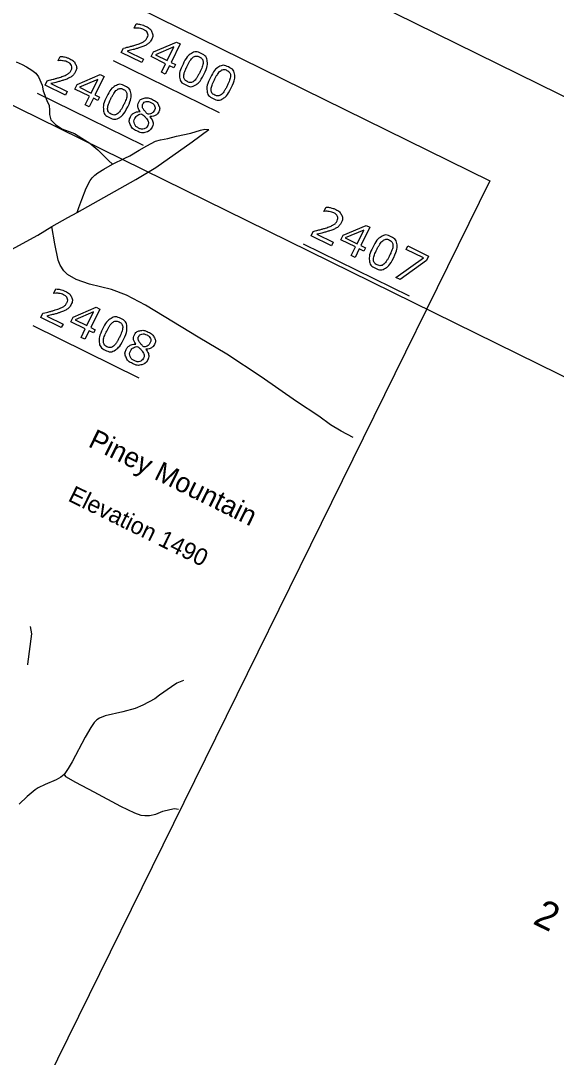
# Model space of a CAD drawing. Extents: x 1428428 to 1430511, y 857911 to 859585.
# Drawn here: x 1429265.4 to 1429384.6, y 859219.8 to 859450.7 of the extents above; entities that cross this region are included whole.
import ezdxf

# ---------------------------------------------------------------- set-up
doc = ezdxf.new("R2010")
doc.units = 0
for name, color, linetype in [('CTL Sheet Border CELL', 7, 'Continuous'), ('CTL Sheet Text', 7, 'Continuous'), ('Default', 7, 'Continuous'), ('Exist Hydrographic Misc Water Feature', 7, 'Continuous'), ('Exist Road Non-System Type 51', 7, 'Continuous'), ('Exist Road Secondary Type 51 Attributed', 7, 'Continuous'), ('Scratch_Level_3', 7, 'Continuous'), ('Sheet Title CELL', 7, 'Continuous')]:
    doc.layers.add(name, color=color, linetype=linetype)

msp = doc.modelspace()

# ---------------------------------------------------------------- linework, layer by layer
at = {"layer": 'CTL Sheet Border CELL'}
msp.add_lwpolyline([(1430484.04, 858893.65), (1429079.63, 859584.7), (1428595.9, 858601.62), (1430000.31, 857910.57)], close=True, dxfattribs=at)
at = {"layer": 'Default'}
for p, q in [((1429285.94, 859441.8), (1429309.51, 859430.2)), ((1429268.99, 859434.56), (1429292.62, 859422.93)), ((1429328.2, 859401), (1429351.8, 859389.38)), ((1429268.04, 859382.76), (1429291.67, 859371.14))]:
    msp.add_line(p, q, dxfattribs=at)
for points in [[(1429290.65, 859448.99), (1429290.6, 859449.02), (1429291.07, 859449.97)], [(1429299.47, 859440.17), (1429298.47, 859440.66), (1429297.54, 859438.77), (1429296.67, 859439.19), (1429297.61, 859441.09), (1429294.38, 859442.67), (1429294.89, 859443.71), (1429300.02, 859445.9), (1429300.85, 859445.49), (1429298.83, 859441.39), (1429299.83, 859440.89), (1429299.47, 859440.17)], [(1429292.29, 859441.35), (1429287.73, 859443.59), (1429288.2, 859444.55)], [(1429289.05, 859443.91), (1429292.67, 859442.13), (1429292.29, 859441.35)], [(1429297.96, 859441.81), (1429299.46, 859444.85), (1429295.35, 859443.1), (1429297.96, 859441.81)], [(1429273.69, 859441.76), (1429273.65, 859441.78), (1429274.11, 859442.73)], [(1429282.52, 859432.93), (1429281.52, 859433.42), (1429280.58, 859431.53), (1429279.72, 859431.95), (1429280.65, 859433.85), (1429277.42, 859435.44), (1429277.94, 859436.47), (1429283.06, 859438.67), (1429283.9, 859438.26), (1429281.87, 859434.15), (1429282.87, 859433.65), (1429282.52, 859432.93)], [(1429275.33, 859434.11), (1429270.77, 859436.35), (1429271.24, 859437.31)], [(1429272.09, 859436.67), (1429275.72, 859434.89), (1429275.33, 859434.11)], [(1429281.01, 859434.57), (1429282.5, 859437.61), (1429278.4, 859435.86), (1429281.01, 859434.57)], [(1429291.91, 859430.42), (1429291.92, 859430.45)], [(1429294.14, 859429.31), (1429294.12, 859429.28)], [(1429332.9, 859408.19), (1429332.86, 859408.22), (1429333.33, 859409.16)], [(1429341.73, 859399.37), (1429340.73, 859399.86), (1429339.8, 859397.96), (1429338.93, 859398.39), (1429339.86, 859400.29), (1429336.64, 859401.87), (1429337.15, 859402.91), (1429342.28, 859405.1), (1429343.11, 859404.69), (1429341.09, 859400.58), (1429342.09, 859400.09), (1429341.73, 859399.37)], [(1429340.22, 859401.01), (1429341.72, 859404.05), (1429337.61, 859402.3), (1429340.22, 859401.01)], [(1429334.55, 859400.55), (1429329.99, 859402.79), (1429330.45, 859403.74)], [(1429331.31, 859403.11), (1429334.93, 859401.33), (1429334.55, 859400.55)], [(1429355.67, 859397.26), (1429349.82, 859393.03), (1429348.85, 859393.51), (1429355, 859397.86), (1429351.18, 859399.74), (1429351.57, 859400.53), (1429356.17, 859398.27), (1429355.67, 859397.26)], [(1429272.75, 859389.96), (1429272.7, 859389.98), (1429273.17, 859390.93)], [(1429274.39, 859382.32), (1429269.83, 859384.56), (1429270.3, 859385.51)], [(1429281.57, 859381.14), (1429280.57, 859381.63), (1429279.64, 859379.73), (1429278.77, 859380.16), (1429279.7, 859382.05), (1429276.48, 859383.64), (1429276.99, 859384.68), (1429282.12, 859386.87), (1429282.95, 859386.46), (1429280.93, 859382.35), (1429281.93, 859381.86), (1429281.57, 859381.14)], [(1429280.06, 859382.78), (1429281.56, 859385.82), (1429277.45, 859384.06), (1429280.06, 859382.78)], [(1429271.15, 859384.88), (1429274.77, 859383.1), (1429274.39, 859382.32)], [(1429290.96, 859378.62), (1429290.97, 859378.65)], [(1429293.19, 859377.52), (1429293.18, 859377.49)]]:
    msp.add_lwpolyline(points, dxfattribs=at)
for points in [[(1429288.2, 859444.55), (1429288.87, 859444.72), (1429289.55, 859444.89), (1429290.23, 859445.06), (1429290.84, 859445.26), (1429292.12, 859445.67), (1429292.69, 859446.01), (1429293.25, 859446.34), (1429293.53, 859446.92), (1429293.79, 859447.44), (1429293.59, 859447.91), (1429293.39, 859448.38), (1429292.77, 859448.68), (1429292.36, 859448.88), (1429291.8, 859448.98), (1429291.25, 859449.07), (1429290.65, 859448.99)], [(1429291.07, 859449.97), (1429291.47, 859449.97), (1429292.07, 859449.83), (1429292.67, 859449.7), (1429293.17, 859449.45), (1429294.21, 859448.94), (1429294.55, 859448.15), (1429294.89, 859447.36), (1429294.47, 859446.51), (1429294.28, 859446.13), (1429294.02, 859445.84), (1429293.76, 859445.56), (1429293.43, 859445.35), (1429293.11, 859445.16), (1429292.74, 859445.01), (1429292.37, 859444.85), (1429291.87, 859444.69), (1429291.15, 859444.45), (1429290.42, 859444.26), (1429289.68, 859444.07), (1429289.05, 859443.91)], [(1429306.13, 859438.72), (1429305.24, 859436.91), (1429304.26, 859436.34), (1429303.27, 859435.77), (1429302.08, 859436.36), (1429300.87, 859436.95), (1429300.73, 859438.09), (1429300.6, 859439.22), (1429301.48, 859441), (1429302.36, 859442.8), (1429303.35, 859443.38), (1429304.33, 859443.96), (1429305.53, 859443.37), (1429306.74, 859442.77), (1429306.87, 859441.63), (1429307, 859440.48), (1429306.13, 859438.72)], [(1429271.24, 859437.31), (1429271.92, 859437.48), (1429272.59, 859437.65), (1429273.27, 859437.82), (1429273.88, 859438.02), (1429275.17, 859438.43), (1429275.73, 859438.77), (1429276.3, 859439.11), (1429276.58, 859439.68), (1429276.84, 859440.2), (1429276.63, 859440.67), (1429276.43, 859441.14), (1429275.81, 859441.44), (1429275.4, 859441.65), (1429274.85, 859441.74), (1429274.3, 859441.83), (1429273.69, 859441.76)], [(1429274.11, 859442.73), (1429274.51, 859442.73), (1429275.11, 859442.59), (1429275.71, 859442.46), (1429276.22, 859442.21), (1429277.25, 859441.7), (1429277.59, 859440.91), (1429277.94, 859440.13), (1429277.52, 859439.27), (1429277.33, 859438.89), (1429277.07, 859438.6), (1429276.81, 859438.32), (1429276.47, 859438.12), (1429276.16, 859437.92), (1429275.79, 859437.77), (1429275.41, 859437.61), (1429274.91, 859437.45), (1429274.2, 859437.22), (1429273.46, 859437.02), (1429272.73, 859436.83), (1429272.09, 859436.67)], [(1429303.93, 859437.25), (1429304.27, 859437.54), (1429304.57, 859438.01), (1429304.87, 859438.48), (1429305.22, 859439.17), (1429305.55, 859439.86), (1429305.75, 859440.4), (1429305.94, 859440.93), (1429305.95, 859441.36), (1429305.96, 859441.79), (1429305.78, 859442.1), (1429305.59, 859442.41), (1429305.16, 859442.62), (1429304.74, 859442.83), (1429304.37, 859442.79), (1429304.01, 859442.75), (1429303.67, 859442.48), (1429303.35, 859442.22), (1429303.03, 859441.71), (1429302.71, 859441.19), (1429302.39, 859440.55), (1429302.05, 859439.85), (1429301.86, 859439.35), (1429301.68, 859438.85), (1429301.66, 859438.39), (1429301.63, 859437.96), (1429301.81, 859437.64), (1429301.99, 859437.32), (1429302.45, 859437.1), (1429302.87, 859436.89), (1429303.24, 859436.93), (1429303.6, 859436.97), (1429303.93, 859437.25)], [(1429312.23, 859435.72), (1429311.34, 859433.91), (1429310.35, 859433.34), (1429309.37, 859432.77), (1429308.18, 859433.35), (1429306.97, 859433.95), (1429306.83, 859435.08), (1429306.7, 859436.22), (1429307.57, 859438), (1429308.46, 859439.8), (1429309.45, 859440.38), (1429310.43, 859440.96), (1429311.63, 859440.37), (1429312.84, 859439.77), (1429312.97, 859438.63), (1429313.1, 859437.48), (1429312.23, 859435.72)], [(1429310.03, 859434.25), (1429310.37, 859434.54), (1429310.67, 859435.01), (1429310.97, 859435.48), (1429311.31, 859436.17), (1429311.65, 859436.86), (1429311.85, 859437.4), (1429312.04, 859437.93), (1429312.05, 859438.36), (1429312.06, 859438.79), (1429311.88, 859439.1), (1429311.69, 859439.41), (1429311.26, 859439.62), (1429310.84, 859439.83), (1429310.47, 859439.79), (1429310.11, 859439.75), (1429309.77, 859439.47), (1429309.45, 859439.22), (1429309.13, 859438.7), (1429308.81, 859438.19), (1429308.49, 859437.55), (1429308.14, 859436.85), (1429307.96, 859436.35), (1429307.78, 859435.85), (1429307.75, 859435.39), (1429307.73, 859434.96), (1429307.91, 859434.64), (1429308.09, 859434.32), (1429308.55, 859434.1), (1429308.97, 859433.89), (1429309.34, 859433.93), (1429309.7, 859433.97), (1429310.03, 859434.25)], [(1429289.18, 859431.48), (1429288.28, 859429.67), (1429287.3, 859429.1), (1429286.31, 859428.53), (1429285.12, 859429.12), (1429283.91, 859429.71), (1429283.78, 859430.85), (1429283.64, 859431.98), (1429284.52, 859433.76), (1429285.4, 859435.56), (1429286.39, 859436.14), (1429287.38, 859436.72), (1429288.57, 859436.13), (1429289.78, 859435.54), (1429289.91, 859434.39), (1429290.04, 859433.24), (1429289.18, 859431.48)], [(1429286.98, 859430.01), (1429287.32, 859430.3), (1429287.62, 859430.77), (1429287.92, 859431.24), (1429288.26, 859431.94), (1429288.6, 859432.62), (1429288.79, 859433.16), (1429288.98, 859433.69), (1429288.99, 859434.13), (1429289.01, 859434.55), (1429288.82, 859434.86), (1429288.64, 859435.17), (1429288.21, 859435.38), (1429287.78, 859435.59), (1429287.42, 859435.55), (1429287.05, 859435.51), (1429286.71, 859435.24), (1429286.4, 859434.98), (1429286.07, 859434.47), (1429285.75, 859433.96), (1429285.44, 859433.31), (1429285.09, 859432.61), (1429284.91, 859432.11), (1429284.72, 859431.61), (1429284.7, 859431.15), (1429284.67, 859430.73), (1429284.86, 859430.41), (1429285.04, 859430.09), (1429285.49, 859429.86), (1429285.91, 859429.65), (1429286.28, 859429.69), (1429286.65, 859429.73), (1429286.98, 859430.01)], [(1429291.92, 859430.45), (1429291.52, 859431), (1429291.43, 859431.47), (1429291.34, 859431.95), (1429291.59, 859432.46), (1429291.96, 859433.22), (1429292.84, 859433.42), (1429293.71, 859433.62), (1429294.67, 859433.14), (1429295.68, 859432.65), (1429296.04, 859431.87), (1429296.41, 859431.09), (1429296.04, 859430.34), (1429295.82, 859429.89), (1429295.31, 859429.59), (1429294.81, 859429.29), (1429294.14, 859429.31)], [(1429295.15, 859430.77), (1429295.38, 859431.26), (1429295.15, 859431.73), (1429294.92, 859432.2), (1429294.34, 859432.48), (1429293.77, 859432.76), (1429293.27, 859432.67), (1429292.77, 859432.58), (1429292.55, 859432.12), (1429292.39, 859431.79), (1429292.45, 859431.47), (1429292.52, 859431.14), (1429292.8, 859430.77), (1429292.93, 859430.61), (1429293.18, 859430.32), (1429293.43, 859430.03), (1429293.68, 859429.8), (1429294.28, 859429.88), (1429294.61, 859430.12), (1429294.94, 859430.35), (1429295.15, 859430.77)], [(1429294.6, 859426.96), (1429294.17, 859426.09), (1429293.21, 859425.84), (1429292.24, 859425.6), (1429291.21, 859426.11), (1429290.12, 859426.65), (1429289.74, 859427.53), (1429289.37, 859428.41), (1429289.81, 859429.3), (1429290.08, 859429.86), (1429290.63, 859430.15), (1429291.18, 859430.44), (1429291.91, 859430.42)], [(1429293.63, 859427.33), (1429293.84, 859427.75), (1429293.78, 859428.09), (1429293.72, 859428.43), (1429293.31, 859428.94), (1429293.14, 859429.15), (1429292.93, 859429.36), (1429292.72, 859429.57), (1429292.37, 859429.93), (1429291.86, 859429.91), (1429291.43, 859429.65), (1429290.99, 859429.39), (1429290.76, 859428.91), (1429290.46, 859428.3), (1429290.68, 859427.7), (1429290.91, 859427.09), (1429291.55, 859426.78), (1429292.22, 859426.45), (1429292.78, 859426.6), (1429293.34, 859426.74), (1429293.63, 859427.33)], [(1429294.12, 859429.28), (1429294.63, 859428.7), (1429294.76, 859428.14), (1429294.9, 859427.57), (1429294.6, 859426.96)], [(1429333.33, 859409.16), (1429333.72, 859409.16), (1429334.33, 859409.03), (1429334.93, 859408.9), (1429335.43, 859408.65), (1429336.46, 859408.14), (1429336.81, 859407.35), (1429337.15, 859406.56), (1429336.73, 859405.71), (1429336.54, 859405.33), (1429336.28, 859405.04), (1429336.02, 859404.76), (1429335.68, 859404.55), (1429335.37, 859404.36), (1429335, 859404.21), (1429334.63, 859404.05), (1429334.13, 859403.89), (1429333.41, 859403.65), (1429332.67, 859403.46), (1429331.94, 859403.27), (1429331.31, 859403.11)], [(1429330.45, 859403.74), (1429331.13, 859403.92), (1429331.81, 859404.09), (1429332.49, 859404.26), (1429333.1, 859404.46), (1429334.38, 859404.87), (1429334.94, 859405.21), (1429335.51, 859405.54), (1429335.79, 859406.12), (1429336.05, 859406.64), (1429335.85, 859407.11), (1429335.65, 859407.57), (1429335.03, 859407.88), (1429334.61, 859408.08), (1429334.06, 859408.18), (1429333.51, 859408.27), (1429332.9, 859408.19)], [(1429348.39, 859397.92), (1429347.5, 859396.11), (1429346.51, 859395.54), (1429345.53, 859394.97), (1429344.34, 859395.55), (1429343.12, 859396.15), (1429342.99, 859397.28), (1429342.86, 859398.42), (1429343.73, 859400.2), (1429344.62, 859402), (1429345.6, 859402.58), (1429346.59, 859403.16), (1429347.79, 859402.57), (1429349, 859401.97), (1429349.13, 859400.83), (1429349.26, 859399.68), (1429348.39, 859397.92)], [(1429346.19, 859396.45), (1429346.53, 859396.74), (1429346.83, 859397.21), (1429347.13, 859397.68), (1429347.47, 859398.37), (1429347.81, 859399.06), (1429348, 859399.6), (1429348.2, 859400.13), (1429348.21, 859400.56), (1429348.22, 859400.99), (1429348.03, 859401.3), (1429347.85, 859401.61), (1429347.42, 859401.82), (1429347, 859402.03), (1429346.63, 859401.99), (1429346.27, 859401.95), (1429345.93, 859401.67), (1429345.61, 859401.42), (1429345.29, 859400.9), (1429344.97, 859400.39), (1429344.65, 859399.75), (1429344.3, 859399.05), (1429344.12, 859398.55), (1429343.93, 859398.05), (1429343.91, 859397.59), (1429343.89, 859397.16), (1429344.07, 859396.84), (1429344.25, 859396.52), (1429344.7, 859396.3), (1429345.13, 859396.09), (1429345.49, 859396.13), (1429345.86, 859396.17), (1429346.19, 859396.45)], [(1429270.3, 859385.51), (1429270.97, 859385.69), (1429271.65, 859385.86), (1429272.33, 859386.03), (1429272.94, 859386.23), (1429274.22, 859386.64), (1429274.79, 859386.98), (1429275.35, 859387.31), (1429275.63, 859387.89), (1429275.89, 859388.41), (1429275.69, 859388.88), (1429275.49, 859389.34), (1429274.87, 859389.65), (1429274.45, 859389.85), (1429273.9, 859389.94), (1429273.35, 859390.03), (1429272.75, 859389.96)], [(1429273.17, 859390.93), (1429273.57, 859390.93), (1429274.17, 859390.8), (1429274.77, 859390.67), (1429275.27, 859390.42), (1429276.31, 859389.91), (1429276.65, 859389.12), (1429276.99, 859388.33), (1429276.57, 859387.48), (1429276.38, 859387.09), (1429276.12, 859386.81), (1429275.86, 859386.53), (1429275.53, 859386.32), (1429275.21, 859386.13), (1429274.84, 859385.97), (1429274.47, 859385.82), (1429273.97, 859385.66), (1429273.25, 859385.42), (1429272.52, 859385.23), (1429271.78, 859385.04), (1429271.15, 859384.88)], [(1429288.23, 859379.69), (1429287.34, 859377.88), (1429286.35, 859377.31), (1429285.37, 859376.74), (1429284.18, 859377.32), (1429282.97, 859377.92), (1429282.83, 859379.05), (1429282.7, 859380.19), (1429283.57, 859381.97), (1429284.46, 859383.77), (1429285.45, 859384.35), (1429286.43, 859384.93), (1429287.63, 859384.34), (1429288.84, 859383.74), (1429288.97, 859382.6), (1429289.1, 859381.45), (1429288.23, 859379.69)], [(1429286.03, 859378.22), (1429286.37, 859378.51), (1429286.67, 859378.98), (1429286.97, 859379.44), (1429287.31, 859380.14), (1429287.65, 859380.83), (1429287.85, 859381.36), (1429288.04, 859381.9), (1429288.05, 859382.33), (1429288.06, 859382.76), (1429287.88, 859383.07), (1429287.69, 859383.38), (1429287.26, 859383.59), (1429286.84, 859383.8), (1429286.47, 859383.76), (1429286.11, 859383.72), (1429285.77, 859383.44), (1429285.45, 859383.18), (1429285.13, 859382.67), (1429284.81, 859382.16), (1429284.49, 859381.52), (1429284.14, 859380.81), (1429283.96, 859380.31), (1429283.78, 859379.81), (1429283.75, 859379.36), (1429283.73, 859378.93), (1429283.91, 859378.61), (1429284.09, 859378.29), (1429284.54, 859378.07), (1429284.97, 859377.86), (1429285.34, 859377.9), (1429285.7, 859377.94), (1429286.03, 859378.22)], [(1429290.97, 859378.65), (1429290.57, 859379.21), (1429290.48, 859379.68), (1429290.39, 859380.15), (1429290.64, 859380.67), (1429291.02, 859381.43), (1429291.89, 859381.63), (1429292.76, 859381.82), (1429293.73, 859381.35), (1429294.74, 859380.85), (1429295.1, 859380.07), (1429295.46, 859379.3), (1429295.1, 859378.55), (1429294.87, 859378.09), (1429294.37, 859377.79), (1429293.87, 859377.49), (1429293.19, 859377.52)], [(1429294.2, 859378.98), (1429294.44, 859379.46), (1429294.21, 859379.93), (1429293.97, 859380.4), (1429293.4, 859380.69), (1429292.83, 859380.97), (1429292.33, 859380.88), (1429291.83, 859380.79), (1429291.6, 859380.32), (1429291.44, 859380), (1429291.51, 859379.67), (1429291.58, 859379.34), (1429291.86, 859378.98), (1429291.98, 859378.81), (1429292.23, 859378.53), (1429292.48, 859378.24), (1429292.74, 859378.01), (1429293.33, 859378.09), (1429293.66, 859378.32), (1429293.99, 859378.56), (1429294.2, 859378.98)], [(1429293.66, 859375.17), (1429293.23, 859374.29), (1429292.26, 859374.05), (1429291.3, 859373.81), (1429290.27, 859374.31), (1429289.17, 859374.85), (1429288.8, 859375.74), (1429288.43, 859376.62), (1429288.86, 859377.5), (1429289.14, 859378.06), (1429289.69, 859378.36), (1429290.24, 859378.65), (1429290.96, 859378.62)], [(1429292.69, 859375.54), (1429292.89, 859375.95), (1429292.83, 859376.29), (1429292.77, 859376.63), (1429292.36, 859377.15), (1429292.2, 859377.35), (1429291.99, 859377.57), (1429291.77, 859377.78), (1429291.43, 859378.14), (1429290.91, 859378.11), (1429290.48, 859377.86), (1429290.05, 859377.6), (1429289.81, 859377.12), (1429289.51, 859376.51), (1429289.74, 859375.91), (1429289.96, 859375.3), (1429290.61, 859374.98), (1429291.27, 859374.66), (1429291.83, 859374.8), (1429292.4, 859374.95), (1429292.69, 859375.54)], [(1429293.18, 859377.49), (1429293.68, 859376.91), (1429293.82, 859376.34), (1429293.96, 859375.78), (1429293.66, 859375.17)]]:
    msp.add_open_spline(points, degree=3, dxfattribs=at)
at = {"layer": 'Exist Hydrographic Misc Water Feature'}
msp.add_lwpolyline([(1429266.9, 859307.2), (1429266.96, 859307.39), (1429267.8, 859314.13), (1429267.53, 859315.75)], dxfattribs=at)
at = {"layer": 'Exist Road Non-System Type 51'}
for points in [[(1429264.36, 859441.55), (1429265.69, 859440.94), (1429266.63, 859440.43), (1429267.83, 859439.64), (1429268.7, 859439.01), (1429269.28, 859438.18), (1429270.11, 859436.34), (1429270.36, 859435.03), (1429271.14, 859432.91), (1429271.69, 859431.8), (1429271.77, 859430.77), (1429271.74, 859429.8), (1429272.04, 859428.61), (1429273.12, 859427.58), (1429274.5, 859426.56), (1429276.15, 859425.99), (1429277.3, 859425.53), (1429278.98, 859424.5), (1429280.75, 859423.38), (1429282.55, 859421.91), (1429284.9, 859419.56), (1429285.77, 859418.74)], [(1429275.02, 859282.77), (1429275.31, 859282.34), (1429277.53, 859281.11), (1429281.6, 859278.96), (1429287.6, 859275.73), (1429290.71, 859274.23), (1429292.12, 859273.77), (1429293, 859273.67), (1429294.03, 859273.7), (1429295.42, 859274), (1429296.98, 859274.6), (1429298.54, 859274.97), (1429299.56, 859275.2), (1429300.5, 859275.1)]]:
    msp.add_lwpolyline(points, dxfattribs=at)
at = {"layer": 'Exist Road Secondary Type 51 Attributed'}
for points in [[(1429277.95, 859407.98), (1429290.94, 859415.31), (1429295.4, 859417.95), (1429303.53, 859423.68), (1429307.26, 859426.42)], [(1429288.52, 859420.04), (1429289.61, 859420.55), (1429291.72, 859421.87), (1429293.41, 859422.82), (1429295.38, 859423.85), (1429296.48, 859424.13), (1429298.12, 859424.43), (1429300.05, 859424.95), (1429303.25, 859425.65), (1429305.4, 859426.31), (1429306.36, 859426.52), (1429307.26, 859426.42)], [(1429277.95, 859407.98), (1429278.3, 859409.06), (1429278.93, 859410.85), (1429279.95, 859413.35), (1429280.83, 859415.07), (1429281.25, 859415.72), (1429281.85, 859416.28), (1429282.55, 859416.83), (1429283.86, 859417.61), (1429285.77, 859418.74), (1429288.52, 859420.04)], [(1429272.28, 859404.82), (1429275.87, 859406.83), (1429277.95, 859407.98)], [(1429244.84, 859383.94), (1429245.65, 859385), (1429248.28, 859388.09), (1429250.88, 859390.86), (1429252.69, 859392.72), (1429255.06, 859394.56), (1429257.15, 859396.08), (1429258.96, 859397.31), (1429261.69, 859398.83), (1429269.17, 859402.95), (1429272.28, 859404.82)], [(1429326.76, 859365.89), (1429318.87, 859371.33), (1429311.26, 859376.39), (1429304.89, 859380.17), (1429297.32, 859384.82), (1429293.14, 859387.34), (1429288.88, 859389.55), (1429285.59, 859390.81), (1429280.63, 859392.03), (1429277.73, 859393.03), (1429275.73, 859394.19), (1429274.92, 859394.95), (1429274.1, 859396.25), (1429273.65, 859397.36), (1429272.96, 859401.02), (1429272.28, 859404.82)], [(1429339.37, 859357.87), (1429336.71, 859359.3), (1429334.29, 859360.7), (1429331.75, 859362.61), (1429326.76, 859365.89)], [(1429301.58, 859303.75), (1429300.1, 859303.12), (1429298.93, 859302.31), (1429296.25, 859300.47), (1429295.21, 859299.66), (1429292.5, 859298.27), (1429290.83, 859297.47), (1429288.11, 859296.73), (1429284.14, 859295.83), (1429282.9, 859295.35), (1429282.3, 859295), (1429281.71, 859294.37), (1429280.99, 859293.28), (1429279.67, 859291.1), (1429276.77, 859285.62), (1429275.93, 859284.16), (1429275.02, 859282.77), (1429274.27, 859282.23), (1429273.24, 859281.63), (1429270.8, 859280.6), (1429269.24, 859279.8), (1429268.58, 859279.39), (1429266.77, 859277.88), (1429265.01, 859276.17)]]:
    msp.add_lwpolyline(points, dxfattribs=at)
at = {"layer": 'Scratch_Level_3'}
msp.add_line((1429096.55, 859514.03), (1429536.95, 859297.33), dxfattribs=at)
at = {"layer": 'Sheet Title CELL'}
for p, q in [((1429091.66, 859551.91), (1429369.81, 859415.05)), ((1429369.81, 859415.05), (1429228.53, 859127.93))]:
    msp.add_line(p, q, dxfattribs=at)

# ---------------------------------------------------------------- texts
at = {"layer": 'CTL Sheet Text'}
msp.add_text('2              GPS B4846-2         858534.9290     1429921.2587          1034.09         17+36.69         28.69 RT', height=6.25, rotation=333.8001, dxfattribs=at).set_placement((1429379.12, 859249.68))
at = {"layer": 'Default'}
for s, height, p in [('Piney Mountain', 4.4, (1429280.14, 859355.93)), ('Elevation 1490', 3.8, (1429275.66, 859343.84))]:
    msp.add_text(s, height=height, rotation=333.8001, dxfattribs=at).set_placement(p)

doc.saveas('drawing.dxf')
